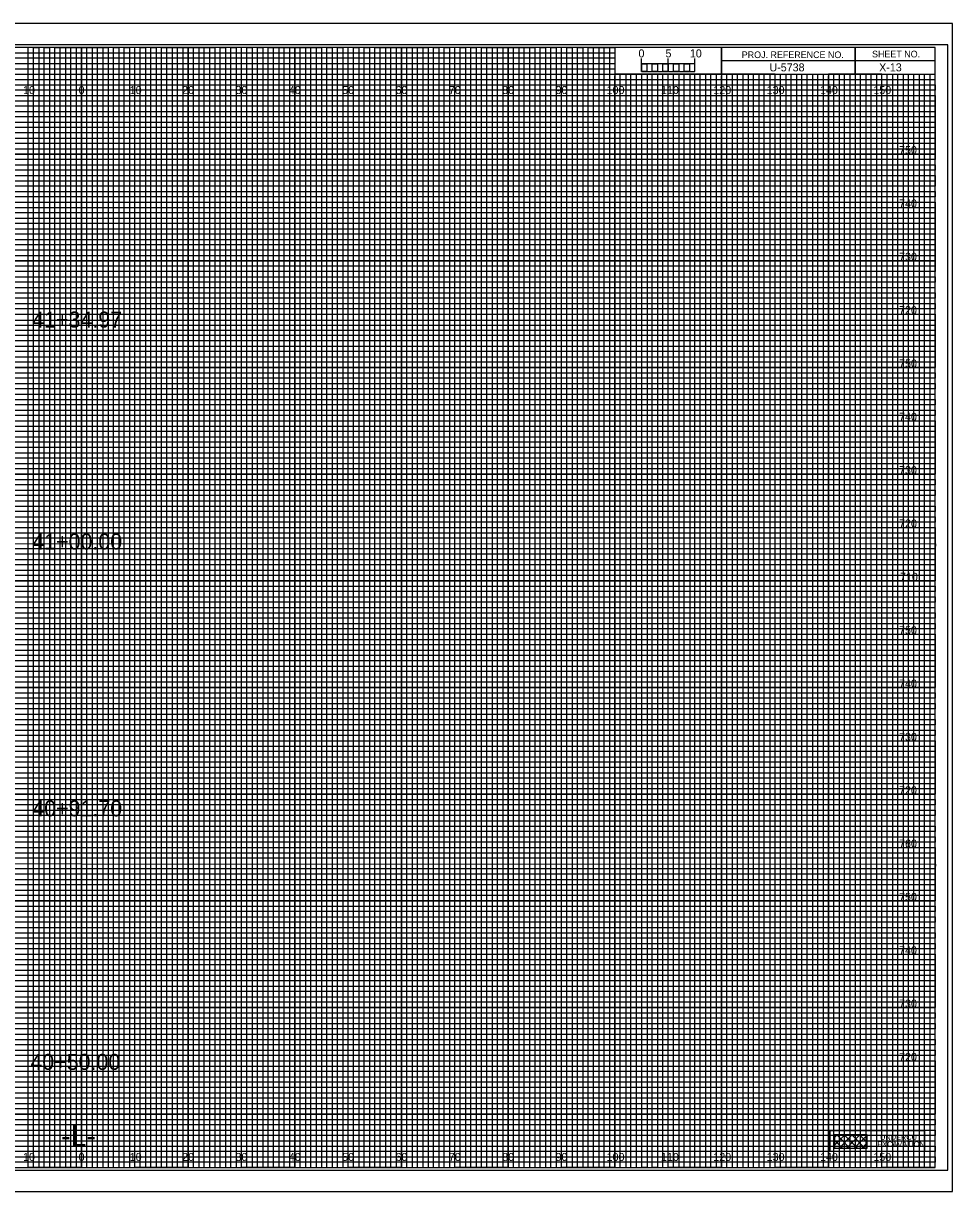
# Model space of a CAD drawing. Extents: x -13 to 323, y 655 to 874.
# Drawn here: x 149.1 to 323.3, y 655.5 to 874.5 of the extents above; entities that cross this region are included whole.
import ezdxf

# ---------------------------------------------------------------- set-up
doc = ezdxf.new("R2010")
doc.units = 0
for name, color, linetype in [('Prop CMT Bridge Metal Rail', 7, 'Continuous'), ('Prop CMT Conc Surface', 7, 'Continuous'), ('Prop CMT Guardrail Graphics', 7, 'Continuous'), ('Prop CMT Slope Grass', 7, 'Continuous'), ('Prop XS Alignment Label', 7, 'Continuous'), ('Prop XS Bar Scale Labels', 7, 'Continuous'), ('Prop XS DDE', 7, 'Continuous'), ('Prop XS DDE Elevations', 7, 'Continuous'), ('Prop XS DDE Text', 7, 'Continuous'), ('Prop XS Hydro Elevations', 7, 'Continuous'), ('Prop XS Hydro Slope Text', 7, 'Continuous'), ('Prop XS Hydro Typical Ditch Data', 7, 'Continuous'), ('Prop XS SE Text', 7, 'Continuous'), ('Prop XS Side Slope Text', 7, 'Continuous'), ('Prop XS Undercut Exc', 7, 'Continuous'), ('Prop XS Undercut Exc Hatch', 7, 'Continuous'), ('Prop XSC Text', 7, 'Continuous'), ('Scratch_Level_1', 7, 'Continuous'), ('Scratch_Level_3', 7, 'Continuous'), ('Scratch_Level_4', 7, 'Continuous')]:
    doc.layers.add(name, color=color, linetype=linetype)

msp = doc.modelspace()

# ---------------------------------------------------------------- linework, layer by layer
at = {"layer": 'Prop CMT Conc Surface'}
for points in [[(300.34, 666.93), (318, 666.93), (318, 663), (300.34, 663)], [(301.16, 663.65), (307.26, 663.65), (307.26, 666.12), (301.16, 666.12)]]:
    msp.add_lwpolyline(points, close=True, dxfattribs=at)
at = {"layer": 'Prop CMT Guardrail Graphics'}
for p, q in [((150, 870), (140, 870)), ((150, 660), (150, 870)), ((170, 870), (160, 870)), ((160, 870), (160, 660)), ((170, 660), (170, 870)), ((190, 870), (180, 870)), ((180, 870), (180, 660)), ((190, 660), (190, 870)), ((210, 870), (200, 870)), ((200, 870), (200, 660)), ((210, 660), (210, 870)), ((230, 870), (220, 870)), ((220, 870), (220, 660)), ((230, 660), (230, 870)), ((250, 870), (240, 870)), ((240, 870), (240, 660)), ((250, 660), (250, 870)), ((260, 870), (260, 660)), ((270, 660), (270, 865)), ((290, 865), (280, 865)), ((280, 865), (280, 660)), ((290, 660), (290, 865)), ((310, 865), (300, 865)), ((300, 865), (300, 660)), ((310, 660), (310, 865)), ((160, 660), (150, 660)), ((180, 660), (170, 660)), ((200, 660), (190, 660)), ((220, 660), (210, 660)), ((240, 660), (230, 660)), ((260, 660), (250, 660)), ((280, 660), (270, 660)), ((300, 660), (290, 660)), ((320, 660), (310, 660)), ((320, 660), (320, 660))]:
    msp.add_line(p, q, dxfattribs=at)
for points in [[(0, 860), (320, 860), (320, 850), (0, 850)], [(0, 840), (320, 840), (320, 830), (0, 830)], [(0, 820), (320, 820), (320, 810), (0, 810)], [(0, 800), (320, 800), (320, 790), (0, 790)], [(0, 780), (320, 780), (320, 770), (0, 770)], [(0, 760), (320, 760), (320, 750), (0, 750)], [(0, 740), (320, 740), (320, 730), (0, 730)], [(0, 720), (320, 720), (320, 710), (0, 710)], [(0, 700), (320, 700), (320, 690), (0, 690)], [(0, 680), (320, 680), (320, 670), (0, 670)]]:
    msp.add_lwpolyline(points, dxfattribs=at)
at = {"layer": 'Prop CMT Slope Grass'}
for p, q in [((301.16, 665.63), (301.65, 666.12)), ((301.16, 664.21), (303.06, 666.12)), ((301.58, 666.12), (304.05, 663.65)), ((302.01, 663.65), (304.48, 666.12)), ((302.99, 666.12), (305.46, 663.65)), ((303.42, 663.65), (305.89, 666.12)), ((304.41, 666.12), (306.87, 663.65)), ((304.84, 663.65), (307.26, 666.07)), ((305.82, 666.12), (307.26, 664.68)), ((307.24, 666.12), (307.26, 666.09)), ((301.16, 665.12), (302.63, 663.65)), ((301.16, 663.71), (301.22, 663.65)), ((306.25, 663.65), (307.26, 664.66))]:
    msp.add_line(p, q, dxfattribs=at)
at = {"layer": 'Prop XS DDE'}
msp.add_lwpolyline([(-10.8, 659.5), (322.4, 659.5), (322.4, 870.5), (-10.8, 870.5)], close=True, dxfattribs=at)
at = {"layer": 'Prop XS DDE Elevations'}
for p, q in [((323.3, 874.5), (-13.4, 874.5)), ((-13.4, 655.5), (323.3, 655.5))]:
    msp.add_line(p, q, dxfattribs=at)
at = {"layer": 'Prop XS DDE Text'}
for p, q in [((150, 660), (150, 870)), ((160, 660), (160, 870)), ((170, 660), (170, 870)), ((180, 660), (180, 870)), ((190, 660), (190, 870)), ((200, 660), (200, 870)), ((210, 660), (210, 870)), ((220, 660), (220, 870)), ((230, 660), (230, 870)), ((240, 660), (240, 870)), ((250, 660), (250, 870)), ((260, 660), (260, 864.69)), ((270, 660), (270, 864.69)), ((280, 660), (280, 864.69)), ((290, 660), (290, 864.69)), ((300, 660), (300, 864.69)), ((310, 660), (310, 864.69)), ((0, 860), (320, 860)), ((0, 850), (320, 850)), ((0, 840), (320, 840)), ((0, 830), (320, 830)), ((0, 820), (320, 820)), ((0, 810), (320, 810)), ((0, 800), (320, 800)), ((0, 790), (320, 790)), ((0, 780), (320, 780)), ((0, 770), (320, 770)), ((0, 760), (320, 760)), ((0, 750), (320, 750)), ((0, 740), (320, 740)), ((0, 730), (320, 730)), ((0, 720), (320, 720)), ((0, 710), (320, 710)), ((0, 700), (320, 700)), ((0, 690), (320, 690)), ((0, 680), (320, 680)), ((0, 670), (320, 670))]:
    msp.add_line(p, q, dxfattribs=at)
at = {"layer": 'Prop XS Hydro Elevations'}
for p, q in [((267, 865), (266.01, 865)), ((266.01, 865), (266.01, 660)), ((267, 660), (267, 865)), ((269, 865), (268, 865)), ((268, 865), (268, 660)), ((269, 660), (269, 865)), ((266.01, 660), (265, 660)), ((268, 660), (267, 660))]:
    msp.add_line(p, q, dxfattribs=at)
for points in [[(150, 660), (151, 660), (151, 870), (152, 870), (152, 660)], [(152, 660), (153, 660), (153, 870), (154, 870), (154, 660)], [(155, 660), (156, 660), (156, 870), (157, 870), (157, 660)], [(157, 660), (158, 660), (158, 870), (159, 870), (159, 660)], [(160, 660), (161, 660), (161, 870), (162, 870), (162, 660)], [(162, 660), (163, 660), (163, 870), (164, 870), (164, 660)], [(165, 660), (166, 660), (166, 870), (167, 870), (167, 660)], [(167, 660), (168, 660), (168, 870), (169, 870), (169, 660)], [(170, 660), (171, 660), (171, 870), (172, 870), (172, 660)], [(172, 660), (173, 660), (173, 870), (174, 870), (174, 660)], [(175, 660), (176, 660), (176, 870), (177, 870), (177, 660)], [(177, 660), (178, 660), (178, 870), (179, 870), (179, 660)], [(180, 660), (181, 660), (181, 870), (182, 870), (182, 660)], [(182, 660), (183, 660), (183, 870), (184, 870), (184, 660)], [(185, 660), (186, 660), (186, 870), (187, 870), (187, 660)], [(187, 660), (188, 660), (188, 870), (189, 870), (189, 660)], [(190, 660), (191, 660), (191, 870), (192, 870), (192, 660)], [(192, 660), (193, 660), (193, 870), (194, 870), (194, 660)], [(195, 660), (196, 660), (196, 870), (197, 870), (197, 660)], [(197, 660), (198, 660), (198, 870), (199, 870), (199, 660)], [(200, 660), (201, 660), (201, 870), (202, 870), (202, 660)], [(202, 660), (203, 660), (203, 870), (204, 870), (204, 660)], [(205, 660), (206, 660), (206, 870), (207, 870), (207, 660)], [(207, 660), (208, 660), (208, 870), (209, 870), (209, 660)], [(210, 660), (211, 660), (211, 870), (212, 870), (212, 660)], [(212, 660), (213, 660), (213, 870), (214, 870), (214, 660)], [(215, 660), (216, 660), (216, 870), (217, 870), (217, 660)], [(217, 660), (218, 660), (218, 870), (219, 870), (219, 660)], [(220, 660), (221, 660), (221, 870), (222, 870), (222, 660)], [(222, 660), (223, 660), (223, 870), (224, 870), (224, 660)], [(225, 660), (226, 660), (226, 870), (227, 870), (227, 660)], [(227, 660), (228, 660), (228, 870), (229, 870), (229, 660)], [(230, 660), (231, 660), (231, 870), (232, 870), (232, 660)], [(232, 660), (233, 660), (233, 870), (234, 870), (234, 660)], [(235, 660), (236, 660), (236, 870), (237, 870), (237, 660)], [(237, 660), (238, 660), (238, 870), (239, 870), (239, 660)], [(240, 660), (241, 660), (241, 870), (242, 870), (242, 660)], [(242, 660), (243, 660), (243, 870), (244, 870), (244, 660)], [(245, 660), (246, 660), (246, 870), (247, 870), (247, 660)], [(247, 660), (248, 660), (248, 870), (249, 870), (249, 660)], [(250, 660), (251, 660), (251, 870), (252, 870), (252, 660)], [(252, 660), (253, 660), (253, 870), (254, 870), (254, 660)], [(255, 660), (256, 660), (256, 870), (257, 870), (257, 660)], [(257, 660), (258, 660), (258, 870), (259, 870), (259, 660)], [(260, 660), (261, 660), (261, 865), (262.02, 865), (262.02, 660)], [(262, 660), (263, 660), (263, 865), (263.99, 865), (263.99, 660)], [(270, 660), (270.98, 660), (270.98, 865), (272, 865), (272, 660)], [(272, 660), (273, 660), (273, 865), (274.05, 865), (274.05, 660)], [(275, 660), (276, 660), (276, 865), (277, 865), (277, 660)], [(277, 660), (278, 660), (278, 865), (279, 865), (279, 660)], [(280, 660), (281, 660), (281, 865), (282, 865), (282, 660)], [(282, 660), (283, 660), (283, 865), (284, 865), (284, 660)], [(285, 660), (286, 660), (286, 865), (287, 865), (287, 660)], [(287, 660), (288, 660), (288, 865), (289, 865), (289, 660)], [(290, 660), (291, 660), (291, 865), (292, 865), (292, 660)], [(292, 660), (293, 660), (293, 865), (294, 865), (294, 660)], [(295, 660), (296, 660), (296, 865), (297, 865), (297, 660)], [(297, 660), (298, 660), (298, 865), (299, 865), (299, 660)], [(300, 660), (301, 660), (301, 865), (302, 865), (302, 660)], [(302, 660), (303, 660), (303, 865), (304, 865), (304, 660)], [(305, 660), (306, 660), (306, 865), (307, 865), (307, 660)], [(307, 660), (308, 660), (308, 865), (309, 865), (309, 660)], [(310, 660), (311, 660), (311, 865), (312, 865), (312, 660)], [(312, 660), (313, 660), (313, 865), (314, 865), (314, 660)], [(315, 660), (316, 660), (316, 865), (317, 865), (317, 660)], [(317, 660), (318, 660), (318, 865), (319, 865), (319, 660)]]:
    msp.add_lwpolyline(points, dxfattribs=at)
at = {"layer": 'Prop XS Hydro Slope Text'}
for p, q in [((305, 870), (305, 865)), ((305, 865), (305, 870)), ((280, 867.5), (280, 865)), ((320, 867.49), (280, 867.49)), ((280, 865), (320, 865))]:
    msp.add_line(p, q, dxfattribs=at)
for points in [[(320, 870), (0, 870), (0, 660), (320, 660)], [(280, 870), (260, 870), (260, 865.03), (280, 865.03)], [(320, 870), (280, 870), (280, 865), (320, 865)]]:
    msp.add_lwpolyline(points, close=True, dxfattribs=at)
at = {"layer": 'Prop XS Hydro Typical Ditch Data'}
for p, q in [((0, 869), (260, 869)), ((260, 867.98), (0, 867.98)), ((260, 869), (260, 867.98)), ((0, 867), (260, 867)), ((260, 865.89), (0, 865.89)), ((260, 867), (260, 865.89)), ((0, 864), (320, 864))]:
    msp.add_line(p, q, dxfattribs=at)
for points in [[(0, 863), (270, 863), (320, 863), (320, 862), (0, 862)], [(0, 861), (320, 861), (320, 859), (0, 859)], [(0, 858), (320, 858), (320, 857), (0, 856.98)], [(0, 856), (320, 856), (320, 854), (0, 854)], [(0, 853), (320, 853), (320, 852), (0, 852)], [(0, 851), (320, 851), (320, 849), (0, 849)], [(0, 848), (320, 848), (320, 847), (0, 847)], [(0, 846), (320, 846), (320, 844), (0, 844)], [(0, 843), (320, 843), (320, 842), (0, 842)], [(0, 841), (320, 841), (320, 839), (0, 839)], [(0, 838), (320, 838), (320, 837), (0, 837)], [(0, 836), (320, 836), (320, 833.95), (320, 833), (320, 832), (0, 832)], [(0, 834), (320, 834), (320, 833), (0, 833)], [(0, 831), (320, 831), (320, 829), (0, 829.03)], [(0, 829.03), (320, 829), (320, 828), (0, 828)], [(0, 827), (320, 827), (320, 826), (0, 826)], [(0, 824), (320, 824), (320, 823), (0, 823)], [(0, 822), (320, 822), (320, 821), (0, 821)], [(-0.07, 818.89), (320, 818.89), (320, 817.88), (-0.07, 817.88)], [(0, 817), (320, 817), (320, 816), (0, 816)], [(0, 814), (320, 814), (320, 813), (0, 813)], [(0, 812), (320, 812), (320, 811), (0, 811)], [(0, 809), (320, 809), (320, 808), (0, 808)], [(0, 807), (320, 807), (320, 806), (0, 806)], [(0, 804), (320, 804), (320, 803), (0, 803)], [(0, 802), (320, 802), (320, 801), (0, 801)], [(0, 799), (320, 799), (319.99, 797.98), (0, 798)], [(0, 797), (320, 797), (320, 796), (0, 796)], [(0, 794), (320, 794), (320, 793), (0, 793)], [(0, 792), (320, 792), (320, 791), (0, 791)], [(0, 789), (320, 789), (320, 788), (0, 788)], [(0, 787), (320, 787), (320, 786), (0, 786)], [(0, 784), (320, 784), (320, 783), (0, 783)], [(0, 782), (320, 782), (320, 781), (0, 781)], [(0, 779), (320, 779), (320, 778), (0, 778)], [(0, 776.99), (320.07, 776.91), (320, 776), (0, 776)], [(0, 774), (320, 774), (320, 773), (0, 773)], [(0, 772), (320, 772), (320, 771), (0, 771)], [(0, 769), (320, 769), (320, 768), (0, 768)], [(0, 767), (320, 767), (320, 766), (0, 766)], [(0, 764), (320, 764), (320, 763), (0, 763)], [(0, 762), (320, 762), (320, 761), (0, 761)], [(0, 759), (320, 759), (320, 758), (0, 758)], [(0, 757), (320, 757), (320, 756), (0, 756)], [(0, 754), (320, 754), (320, 753), (0, 753)], [(0, 752), (320, 752), (320, 751), (0, 751)], [(0, 749), (320, 749), (320, 748), (0, 748)], [(0, 747), (320, 747), (320, 746), (0, 746)], [(0, 744), (320, 744), (320, 743), (0, 743)], [(0, 742), (320, 742), (320, 741), (0, 741)], [(0, 739), (320, 739), (319.99, 737.98), (0, 738)], [(0, 737), (320, 737), (320, 736), (0, 736)], [(0, 734), (320, 734), (320, 733), (0, 733)], [(0, 732), (320, 732), (320, 731), (0, 731)], [(0, 729), (320, 729), (320, 728), (0, 728)], [(0, 727), (320, 727), (320, 726), (0, 726)], [(0, 724), (320, 724), (320, 723), (0, 723)], [(0, 722), (320, 722), (320, 721), (0, 721)], [(0, 719), (320, 719), (320, 718), (0, 718)], [(0, 716.99), (320.07, 716.91), (320, 716), (0, 716)], [(0, 714), (320, 714), (320, 713), (0, 713)], [(0, 712), (320, 712), (320, 711), (0, 711)], [(0, 709), (320, 709), (320, 708), (0, 708)], [(0, 707), (320, 707), (320, 706), (0, 706)], [(0, 704), (320, 704), (320, 703), (0, 703)], [(0, 702), (320, 702), (320, 701), (0, 701)], [(0, 699), (320, 699), (320, 698), (0, 698)], [(0, 697), (320, 697), (320, 696), (0, 696)], [(0, 694), (320, 694), (320, 693), (0, 693)], [(0, 692), (320, 692), (320, 691), (0, 691)], [(0, 689), (320, 689), (320, 688), (0, 688)], [(0, 687), (320, 687), (320, 686), (0, 686)], [(0, 684), (320, 684), (320, 683), (0, 683)], [(0, 682), (320, 682), (320, 681), (0, 681)], [(0, 679), (320, 679), (320, 678), (0, 678)], [(0, 677), (320, 677), (320, 676), (0, 676)], [(0, 674), (320, 674), (320, 673), (0, 673)], [(0, 672), (320, 672), (320, 671), (0, 671)], [(0, 669), (320, 669), (320, 668), (0, 668)], [(0, 667), (320, 667), (320, 666), (0, 666)], [(0, 664), (320, 664), (320, 663), (0, 663)], [(0, 662), (320, 662), (320, 661), (0, 661)]]:
    msp.add_lwpolyline(points, dxfattribs=at)
at = {"layer": 'Prop XS Undercut Exc'}
msp.add_lwpolyline([(-13.4, 655.5), (323.3, 655.5), (323.3, 874.5), (-13.4, 874.5)], close=True, dxfattribs=at)
at = {"layer": 'Scratch_Level_3'}
for p, q in [((265, 865.49), (265, 867.9)), ((265, 866.9), (265, 867.9)), ((270, 865.49), (270, 867.9)), ((275, 865.49), (275, 867.9)), ((275, 866.9), (275, 867.9))]:
    msp.add_line(p, q, dxfattribs=at)
for points in [[(275, 866.9), (265, 866.9), (265, 865.49), (275, 865.49)], [(265, 866.9), (266, 866.9), (266, 865.49), (265, 865.49)], [(267, 866.9), (268, 866.9), (268, 865.49), (267, 865.49)], [(269, 866.9), (270, 866.9), (270, 865.49), (269, 865.49)], [(271, 866.9), (272, 866.9), (272, 865.49), (271, 865.49)], [(273, 866.9), (274, 866.9), (274, 865.49), (273, 865.49)]]:
    msp.add_lwpolyline(points, close=True, dxfattribs=at)
at = {"layer": 'Scratch_Level_4'}
for points in [[(145, 660), (155, 660), (155, 870), (165, 870), (165, 660), (175, 660), (175, 870), (185, 870), (185, 660), (195, 660), (195, 870), (205, 870), (205, 660), (215, 660), (215, 870), (225, 870), (225, 660), (235, 660), (235, 870), (245, 870), (245, 660), (255, 660), (255, 870), (259.93, 870), (260, 870), (260, 865), (264.99, 865), (264.99, 660), (275, 660), (275, 865), (285, 865), (285, 660), (295, 660), (295, 865), (305, 865), (305, 660), (315, 660), (315, 865)], [(0, 865), (275, 865)], [(0, 845), (320, 845), (320, 855), (0, 855)], [(0, 825), (320, 825), (320, 835), (0, 835)], [(0, 805), (320, 805), (320, 815), (0, 815)], [(0, 785), (320, 785), (320, 795), (0, 795)], [(0, 765), (320, 765), (320, 775), (0, 775)], [(0, 745), (320, 745), (320, 755), (0, 755)], [(0, 725), (320, 725), (320, 735), (0, 735)], [(0, 705), (320, 705), (320, 715), (0, 715)], [(0, 685), (320, 685), (320, 695), (0, 695)], [(0, 665), (320, 665), (320, 675), (0, 675)]]:
    msp.add_lwpolyline(points, dxfattribs=at)

# ---------------------------------------------------------------- texts
at = {"layer": 'Prop CMT Bridge Metal Rail'}
for s, p in [('UNDERCUT', (309.7, 665.2)), ('EXCAVATION', (309.18, 663.89))]:
    msp.add_text(s, height=1, dxfattribs=at).set_placement(p)
at = {"layer": 'Prop XS Alignment Label'}
msp.add_text('-L-', height=4, dxfattribs=at).set_placement((156.15, 664))
at = {"layer": 'Prop XS Bar Scale Labels'}
for s, p in [('5', (269.47, 868.12)), ('10', (274.04, 868.12))]:
    msp.add_text(s, height=1.5, dxfattribs=at).set_placement(p)
at = {"layer": 'Prop XS Hydro Slope Text'}
for s, p in [('PROJ. REFERENCE NO.', (283.77, 867.99)), ('SHEET NO.', (308.19, 868.12))]:
    msp.add_text(s, height=1.25, dxfattribs=at).set_placement(p)
at = {"layer": 'Prop XS SE Text'}
for s, p in [('750', (313.26, 850)), ('740', (313.26, 840)), ('730', (313.26, 830)), ('720', (313.26, 820)), ('750', (313.26, 810)), ('740', (313.26, 800)), ('730', (313.26, 790)), ('720', (313.26, 780)), ('710', (313.44, 770)), ('750', (313.26, 760)), ('740', (313.26, 750)), ('730', (313.26, 740)), ('720', (313.26, 730)), ('760', (313.26, 720)), ('750', (313.26, 710)), ('740', (313.26, 700)), ('730', (313.26, 690)), ('720', (313.26, 680))]:
    msp.add_text(s, height=1.5, dxfattribs=at).set_placement(p)
at = {"layer": 'Prop XS Side Slope Text'}
for s, p in [('41+34.97', (150.76, 817.47)), ('41+00.00', (150.77, 775.87)), ('40+91.70', (150.77, 725.85)), ('40+50.00', (150.41, 678.32))]:
    msp.add_text(s, height=3, dxfattribs=at).set_placement(p)
at = {"layer": 'Prop XS Undercut Exc Hatch'}
msp.add_text('X-13', height=1.5, dxfattribs=at).set_placement((309.52, 865.5))
at = {"layer": 'Prop XSC Text'}
msp.add_text('U-5738', height=1.5, dxfattribs=at).set_placement((288.96, 865.5))
at = {"layer": 'Scratch_Level_1'}
for s, p in [('10', (149.04, 861.25)), ('0', (159.45, 861.25)), ('0', (159.45, 861.25)), ('10', (169.04, 861.25)), ('20', (178.86, 861.25)), ('30', (188.86, 861.25)), ('40', (198.86, 861.25)), ('50', (208.86, 861.25)), ('60', (218.86, 861.25)), ('70', (228.86, 861.25)), ('80', (238.86, 861.25)), ('90', (248.86, 861.25)), ('100', (258.44, 861.25)), ('110', (268.62, 861.25)), ('120', (278.44, 861.25)), ('130', (288.44, 861.25)), ('140', (298.44, 861.25)), ('150', (308.44, 861.25)), ('10', (149.04, 661.25)), ('0', (159.45, 661.25)), ('0', (159.45, 661.25)), ('10', (169.04, 661.25)), ('20', (178.86, 661.25)), ('30', (188.86, 661.25)), ('40', (198.86, 661.25)), ('50', (208.86, 661.25)), ('60', (218.86, 661.25)), ('70', (228.86, 661.25)), ('80', (238.86, 661.25)), ('90', (248.86, 661.25)), ('100', (258.44, 661.25)), ('110', (268.62, 661.25)), ('120', (278.44, 661.25)), ('130', (288.44, 661.25)), ('140', (298.44, 661.25)), ('150', (308.44, 661.25))]:
    msp.add_text(s, height=1.5, dxfattribs=at).set_placement(p)
at = {"layer": 'Scratch_Level_3'}
msp.add_text('0', height=1.5, dxfattribs=at).set_placement((264.41, 868.12))

doc.saveas('drawing.dxf')
